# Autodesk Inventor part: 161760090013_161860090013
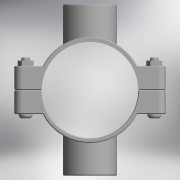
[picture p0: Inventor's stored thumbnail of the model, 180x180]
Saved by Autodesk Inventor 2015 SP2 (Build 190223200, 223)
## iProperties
Created: 2017-05
Part Number: 161760090013_161860090013
Material: Generic
Description: PLASSON DOUBLE SADDLE 90-1.1/4"
Document SubType Name: Modeling
Designer: KIM
Density: 1 g/cm^3
Appearance: Default
Author: KIM
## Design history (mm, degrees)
derived "16176.ipt"
feature "Solid1::16176.ipt"
feature "Solid2::16176.ipt"
tag "TaggingFeature1"
body "Solid1"
body "Solid2"
other parameters: "d0" = 99, "d1" = 141, "d2" = 45, "d4" = 105, "d5" = 0, "d6" = 7.05, "d7" = 141, "d8" = 0.1, "d10" = 0, "d11" = 0.9, "d20" = 0.9, "d23" = 0.9, "d36" = 13, "d37" = 10.4, "d38" = 53, "d39" = 0, "d40" = 3, "d41" = 5, "d42" = 0, "d43" = 8, "d44" = 3, "d45" = 0, "d46" = 0.9, "d52" = 38.952, "d53" = 25, "d54" = 0, "d55" = 32, "d57" = 0, "d58" = 97.2, "d60" = 0, "d62" = 13, "d63" = 10.4, "d66" = 84.2, "d68" = 50.6376, "d69" = 38.952, "d70" = 25, "d71" = 0, "d72" = 32, "d74" = 0, "d75" = 0.9, "B_" = 32, "G_" = 38.952, "L_" = 141, "L_1" = 105, "l_2" = 25
